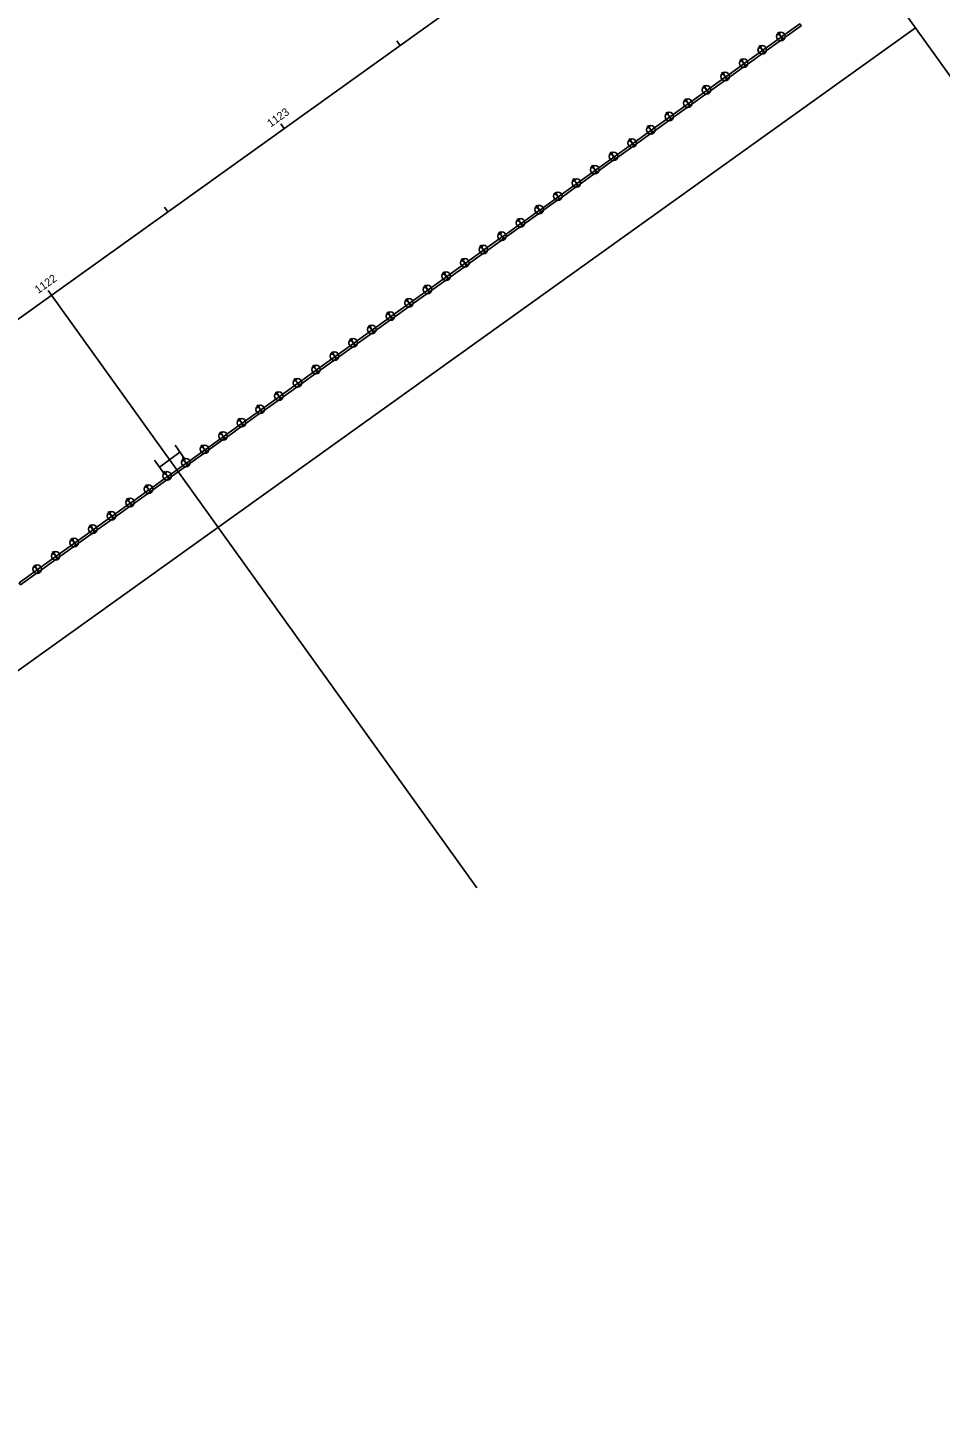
# Model space of a CAD drawing. Extents: x 2079879 to 2092887, y 778083 to 784051.
# Drawn here: x 2084142 to 2084461, y 780721.7 to 781206.9 of the extents above; entities that cross this region are included whole.
import ezdxf

# ---------------------------------------------------------------- set-up
doc = ezdxf.new("R2010")
doc.units = 0
for name, color, linetype in [('SC_Scratch1', 7, 'Continuous'), ('SH_Data', 7, 'Continuous'), ('SH_Text', 7, 'Continuous'), ('XS_X_Pavt', 7, 'Continuous')]:
    doc.layers.add(name, color=color, linetype=linetype)

msp = doc.modelspace()

# ---------------------------------------------------------------- linework, layer by layer
at = {"layer": 'SC_Scratch1'}
for p, q in [((2079923.52, 778084.44), (2085691.45, 782217.74)), ((2084272.23, 781200.72), (2084271.06, 781202.35)), ((2084231.59, 781171.6), (2084230.42, 781173.22)), ((2084190.94, 781142.47), (2084189.78, 781144.1)), ((2084150.3, 781113.35), (2084149.14, 781114.97))]:
    msp.add_line(p, q, dxfattribs=at)
at = {"layer": 'SH_Data'}
for p, q in [((2084394.15, 781288.09), (2084523.01, 781108.28)), ((2083962.54, 780855.77), (2084452.4, 781206.81)), ((2084404.67, 781204.74), (2084404.24, 781205.35)), ((2084398.17, 781200.08), (2084397.74, 781200.69)), ((2084391.67, 781195.42), (2084391.24, 781196.03)), ((2084385.17, 781190.76), (2084384.73, 781191.37)), ((2084378.66, 781186.1), (2084378.23, 781186.71)), ((2084365.66, 781176.78), (2084365.22, 781177.39)), ((2084372.16, 781181.44), (2084371.73, 781182.05)), ((2084359.15, 781172.12), (2084358.72, 781172.74)), ((2084352.65, 781167.46), (2084352.22, 781168.08)), ((2084346.15, 781162.8), (2084345.72, 781163.42)), ((2084339.65, 781158.14), (2084339.21, 781158.76)), ((2084333.14, 781153.48), (2084332.71, 781154.1)), ((2084320.14, 781144.16), (2084319.71, 781144.78)), ((2084313.64, 781139.5), (2084313.2, 781140.12)), ((2084307.13, 781134.84), (2084306.7, 781135.46)), ((2084300.63, 781130.18), (2084300.2, 781130.8)), ((2084294.13, 781125.52), (2084293.69, 781126.14)), ((2084287.62, 781120.86), (2084287.19, 781121.48)), ((2084281.12, 781116.2), (2084280.69, 781116.82)), ((2084150.3, 781113.35), (2084298.97, 780905.89)), ((2084268.12, 781106.88), (2084267.68, 781107.5)), ((2084261.61, 781102.22), (2084261.18, 781102.84)), ((2084255.11, 781097.56), (2084254.68, 781098.18)), ((2084248.61, 781092.9), (2084248.18, 781093.52)), ((2084242.1, 781088.24), (2084241.67, 781088.86)), ((2084235.6, 781083.58), (2084235.17, 781084.2)), ((2084229.1, 781078.92), (2084228.67, 781079.54)), ((2084222.6, 781074.27), (2084222.16, 781074.88)), ((2084216.09, 781069.61), (2084215.66, 781070.22)), ((2084203.09, 781060.29), (2084202.66, 781060.9)), ((2084195.19, 781058.32), (2084188.01, 781053.17)), ((2084196.92, 781055.87), (2084193.47, 781060.77)), ((2084196.3, 781056.03), (2084196.01, 781056.44)), ((2084196.59, 781055.63), (2084196.3, 781056.03)), ((2084189.74, 781050.72), (2084186.29, 781055.63)), ((2084189.79, 781051.37), (2084189.51, 781051.78)), ((2084190.08, 781050.97), (2084189.79, 781051.37)), ((2084183.58, 781046.31), (2084183.15, 781046.92)), ((2084177.08, 781041.65), (2084176.65, 781042.26)), ((2084170.57, 781036.99), (2084170.14, 781037.6)), ((2084164.07, 781032.33), (2084163.64, 781032.94)), ((2084157.57, 781027.67), (2084157.14, 781028.28)), ((2084151.07, 781023.01), (2084150.63, 781023.62))]:
    msp.add_line(p, q, dxfattribs=at)
at = {"layer": 'SH_Text'}
for centre in [(2084405.33, 781203.83), (2084398.82, 781199.17), (2084392.32, 781194.51), (2084385.82, 781189.85), (2084379.32, 781185.19), (2084366.31, 781175.87), (2084372.81, 781180.53), (2084359.81, 781171.21), (2084353.3, 781166.55), (2084346.8, 781161.89), (2084340.3, 781157.23), (2084333.8, 781152.57), (2084327.29, 781147.91), (2084320.79, 781143.25), (2084314.29, 781138.59), (2084307.79, 781133.93), (2084301.28, 781129.27), (2084294.78, 781124.61), (2084288.28, 781119.95), (2084281.77, 781115.29), (2084275.27, 781110.63), (2084268.77, 781105.97), (2084262.27, 781101.31), (2084255.76, 781096.65), (2084249.26, 781091.99), (2084242.76, 781087.33), (2084236.26, 781082.67), (2084229.75, 781078.01), (2084223.25, 781073.35), (2084216.75, 781068.69), (2084203.74, 781059.37), (2084210.24, 781064.03), (2084197.24, 781054.71), (2084190.74, 781050.05), (2084184.23, 781045.39), (2084177.73, 781040.73), (2084171.23, 781036.08), (2084164.72, 781031.42), (2084158.22, 781026.76), (2084151.72, 781022.1), (2084145.22, 781017.44)]:
    msp.add_circle(centre, 1.5, dxfattribs=at)
at = {"layer": 'XS_X_Pavt'}
for points in [[(2084405.54, 781203.68), (2084411.91, 781208.24), (2084412.39, 781207.56), (2084406.02, 781203)], [(2084399.04, 781199.02), (2084405.4, 781203.58), (2084405.89, 781202.9), (2084399.52, 781198.34)], [(2084404.33, 781204.5), (2084405.01, 781204.98), (2084405.04, 781204.95), (2084404.72, 781204.73), (2084405.98, 781202.97), (2084406.29, 781203.2), (2084406.32, 781203.16), (2084405.64, 781202.68), (2084405.62, 781202.71), (2084405.93, 781202.93), (2084404.67, 781204.69), (2084404.36, 781204.47)], [(2084392.53, 781194.36), (2084398.9, 781198.92), (2084399.38, 781198.24), (2084393.02, 781193.68)], [(2084397.83, 781199.84), (2084398.51, 781200.32), (2084398.53, 781200.29), (2084398.22, 781200.07), (2084399.48, 781198.31), (2084399.79, 781198.54), (2084399.82, 781198.5), (2084399.14, 781198.02), (2084399.11, 781198.05), (2084399.43, 781198.27), (2084398.17, 781200.03), (2084397.86, 781199.81)], [(2084386.03, 781189.7), (2084392.4, 781194.26), (2084392.88, 781193.58), (2084386.51, 781189.02)], [(2084391.33, 781195.18), (2084392.01, 781195.66), (2084392.03, 781195.63), (2084391.72, 781195.41), (2084392.98, 781193.65), (2084393.29, 781193.88), (2084393.31, 781193.84), (2084392.64, 781193.36), (2084392.61, 781193.39), (2084392.92, 781193.61), (2084391.67, 781195.37), (2084391.35, 781195.15)], [(2084379.53, 781185.04), (2084385.89, 781189.6), (2084386.38, 781188.92), (2084380.01, 781184.36)], [(2084384.83, 781190.52), (2084385.5, 781191), (2084385.53, 781190.97), (2084385.21, 781190.75), (2084386.47, 781188.99), (2084386.79, 781189.22), (2084386.81, 781189.18), (2084386.13, 781188.7), (2084386.11, 781188.73), (2084386.42, 781188.95), (2084385.16, 781190.71), (2084384.85, 781190.49)], [(2084373.02, 781180.38), (2084379.39, 781184.94), (2084379.88, 781184.26), (2084373.51, 781179.7)], [(2084378.32, 781185.86), (2084379, 781186.34), (2084379.02, 781186.31), (2084378.71, 781186.09), (2084379.97, 781184.33), (2084380.28, 781184.56), (2084380.31, 781184.52), (2084379.63, 781184.04), (2084379.61, 781184.07), (2084379.92, 781184.29), (2084378.66, 781186.05), (2084378.35, 781185.83)], [(2084366.52, 781175.72), (2084372.89, 781180.28), (2084373.37, 781179.6), (2084367.01, 781175.04)], [(2084371.82, 781181.2), (2084372.5, 781181.68), (2084372.52, 781181.65), (2084372.21, 781181.43), (2084373.47, 781179.67), (2084373.78, 781179.9), (2084373.8, 781179.86), (2084373.13, 781179.38), (2084373.1, 781179.41), (2084373.42, 781179.63), (2084372.16, 781181.39), (2084371.84, 781181.17)], [(2084360.02, 781171.06), (2084366.39, 781175.62), (2084366.87, 781174.94), (2084360.5, 781170.38)], [(2084365.32, 781176.54), (2084366, 781177.02), (2084366.02, 781176.99), (2084365.71, 781176.77), (2084366.96, 781175.01), (2084367.28, 781175.24), (2084367.3, 781175.2), (2084366.62, 781174.72), (2084366.6, 781174.75), (2084366.91, 781174.98), (2084365.66, 781176.73), (2084365.34, 781176.51)], [(2084352.31, 781167.22), (2084352.99, 781167.71), (2084353.01, 781167.67), (2084352.7, 781167.45), (2084353.96, 781165.69), (2084354.27, 781165.92), (2084354.3, 781165.88), (2084353.62, 781165.4), (2084353.59, 781165.43), (2084353.91, 781165.66), (2084352.65, 781167.41), (2084352.34, 781167.19)], [(2084353.52, 781166.4), (2084359.88, 781170.96), (2084360.37, 781170.28), (2084354, 781165.72)], [(2084358.82, 781171.88), (2084359.49, 781172.36), (2084359.52, 781172.33), (2084359.2, 781172.11), (2084360.46, 781170.35), (2084360.77, 781170.58), (2084360.8, 781170.54), (2084360.12, 781170.06), (2084360.1, 781170.09), (2084360.41, 781170.32), (2084359.15, 781172.07), (2084358.84, 781171.85)], [(2084345.81, 781162.56), (2084346.49, 781163.05), (2084346.51, 781163.01), (2084346.2, 781162.79), (2084347.46, 781161.03), (2084347.77, 781161.26), (2084347.79, 781161.22), (2084347.12, 781160.74), (2084347.09, 781160.77), (2084347.41, 781161), (2084346.15, 781162.75), (2084345.83, 781162.53)], [(2084347.01, 781161.74), (2084353.38, 781166.3), (2084353.87, 781165.62), (2084347.5, 781161.06)], [(2084339.31, 781157.9), (2084339.98, 781158.39), (2084340.01, 781158.35), (2084339.7, 781158.13), (2084340.95, 781156.37), (2084341.27, 781156.6), (2084341.29, 781156.56), (2084340.61, 781156.08), (2084340.59, 781156.11), (2084340.9, 781156.34), (2084339.64, 781158.09), (2084339.33, 781157.87)], [(2084340.51, 781157.08), (2084346.88, 781161.64), (2084347.36, 781160.97), (2084341, 781156.4)], [(2084332.8, 781153.24), (2084333.48, 781153.73), (2084333.51, 781153.69), (2084333.19, 781153.47), (2084334.45, 781151.71), (2084334.76, 781151.94), (2084334.79, 781151.9), (2084334.11, 781151.42), (2084334.09, 781151.45), (2084334.4, 781151.68), (2084333.14, 781153.43), (2084332.83, 781153.21)], [(2084334.01, 781152.42), (2084340.37, 781156.98), (2084340.86, 781156.31), (2084334.49, 781151.74)], [(2084326.3, 781148.58), (2084326.98, 781149.07), (2084327, 781149.03), (2084326.69, 781148.81), (2084327.95, 781147.05), (2084328.26, 781147.28), (2084328.28, 781147.24), (2084327.61, 781146.76), (2084327.58, 781146.79), (2084327.9, 781147.02), (2084326.64, 781148.77), (2084326.33, 781148.55)], [(2084327.5, 781147.76), (2084333.87, 781152.32), (2084334.36, 781151.65), (2084327.99, 781147.08)], [(2084319.8, 781143.92), (2084320.48, 781144.41), (2084320.5, 781144.37), (2084320.19, 781144.15), (2084321.44, 781142.39), (2084321.76, 781142.62), (2084321.78, 781142.58), (2084321.1, 781142.1), (2084321.08, 781142.13), (2084321.39, 781142.36), (2084320.14, 781144.11), (2084319.82, 781143.89)], [(2084321, 781143.1), (2084327.37, 781147.66), (2084327.85, 781146.99), (2084321.49, 781142.42)], [(2084313.3, 781139.26), (2084313.97, 781139.75), (2084314, 781139.71), (2084313.68, 781139.49), (2084314.94, 781137.73), (2084315.26, 781137.96), (2084315.28, 781137.92), (2084314.6, 781137.44), (2084314.58, 781137.47), (2084314.89, 781137.7), (2084313.63, 781139.45), (2084313.32, 781139.23)], [(2084314.5, 781138.44), (2084320.87, 781143), (2084321.35, 781142.33), (2084314.98, 781137.76)], [(2084301.49, 781129.12), (2084307.86, 781133.68), (2084308.35, 781133.01), (2084301.98, 781128.44)], [(2084306.79, 781134.6), (2084307.47, 781135.09), (2084307.49, 781135.05), (2084307.18, 781134.83), (2084308.44, 781133.07), (2084308.75, 781133.3), (2084308.78, 781133.26), (2084308.1, 781132.78), (2084308.08, 781132.81), (2084308.39, 781133.04), (2084307.13, 781134.79), (2084306.82, 781134.57)], [(2084308, 781133.78), (2084314.36, 781138.34), (2084314.85, 781137.67), (2084308.48, 781133.1)], [(2084294.99, 781124.46), (2084301.36, 781129.02), (2084301.84, 781128.35), (2084295.48, 781123.78)], [(2084300.29, 781129.94), (2084300.97, 781130.43), (2084300.99, 781130.39), (2084300.68, 781130.17), (2084301.94, 781128.41), (2084302.25, 781128.64), (2084302.27, 781128.6), (2084301.6, 781128.12), (2084301.57, 781128.15), (2084301.89, 781128.38), (2084300.63, 781130.13), (2084300.31, 781129.91)], [(2084288.49, 781119.8), (2084294.86, 781124.36), (2084295.34, 781123.69), (2084288.97, 781119.12)], [(2084293.79, 781125.28), (2084294.47, 781125.77), (2084294.49, 781125.73), (2084294.18, 781125.51), (2084295.43, 781123.75), (2084295.75, 781123.98), (2084295.77, 781123.94), (2084295.09, 781123.46), (2084295.07, 781123.49), (2084295.38, 781123.72), (2084294.13, 781125.47), (2084293.81, 781125.25)], [(2084281.99, 781115.14), (2084288.35, 781119.7), (2084288.84, 781119.03), (2084282.47, 781114.46)], [(2084287.29, 781120.62), (2084287.96, 781121.11), (2084287.99, 781121.07), (2084287.67, 781120.85), (2084288.93, 781119.09), (2084289.24, 781119.32), (2084289.27, 781119.28), (2084288.59, 781118.8), (2084288.57, 781118.83), (2084288.88, 781119.06), (2084287.62, 781120.81), (2084287.31, 781120.59)], [(2084275.48, 781110.48), (2084281.85, 781115.04), (2084282.34, 781114.37), (2084275.97, 781109.8)], [(2084280.78, 781115.96), (2084281.46, 781116.45), (2084281.48, 781116.41), (2084281.17, 781116.19), (2084282.43, 781114.43), (2084282.74, 781114.66), (2084282.77, 781114.62), (2084282.09, 781114.14), (2084282.06, 781114.17), (2084282.38, 781114.4), (2084281.12, 781116.15), (2084280.81, 781115.93)], [(2084268.98, 781105.82), (2084275.35, 781110.38), (2084275.83, 781109.71), (2084269.47, 781105.14)], [(2084274.28, 781111.3), (2084274.96, 781111.79), (2084274.98, 781111.75), (2084274.67, 781111.53), (2084275.93, 781109.77), (2084276.24, 781110), (2084276.26, 781109.96), (2084275.59, 781109.48), (2084275.56, 781109.51), (2084275.88, 781109.74), (2084274.62, 781111.49), (2084274.3, 781111.27)], [(2084262.48, 781101.16), (2084268.84, 781105.72), (2084269.33, 781105.05), (2084262.96, 781100.48)], [(2084267.78, 781106.64), (2084268.45, 781107.13), (2084268.48, 781107.09), (2084268.16, 781106.87), (2084269.42, 781105.11), (2084269.74, 781105.34), (2084269.76, 781105.3), (2084269.08, 781104.82), (2084269.06, 781104.85), (2084269.37, 781105.08), (2084268.11, 781106.83), (2084267.8, 781106.61)], [(2084255.97, 781096.5), (2084262.34, 781101.06), (2084262.83, 781100.39), (2084256.46, 781095.82)], [(2084261.27, 781101.98), (2084261.95, 781102.47), (2084261.98, 781102.43), (2084261.66, 781102.21), (2084262.92, 781100.45), (2084263.23, 781100.68), (2084263.26, 781100.64), (2084262.58, 781100.16), (2084262.56, 781100.19), (2084262.87, 781100.42), (2084261.61, 781102.17), (2084261.3, 781101.95)], [(2084249.47, 781091.84), (2084255.84, 781096.4), (2084256.32, 781095.73), (2084249.96, 781091.16)], [(2084254.77, 781097.32), (2084255.45, 781097.81), (2084255.47, 781097.77), (2084255.16, 781097.55), (2084256.42, 781095.79), (2084256.73, 781096.02), (2084256.75, 781095.98), (2084256.08, 781095.5), (2084256.05, 781095.53), (2084256.37, 781095.76), (2084255.11, 781097.51), (2084254.8, 781097.29)], [(2084242.97, 781087.18), (2084249.34, 781091.74), (2084249.82, 781091.07), (2084243.45, 781086.5)], [(2084248.27, 781092.66), (2084248.95, 781093.15), (2084248.97, 781093.11), (2084248.66, 781092.89), (2084249.91, 781091.13), (2084250.23, 781091.36), (2084250.25, 781091.33), (2084249.57, 781090.84), (2084249.55, 781090.87), (2084249.86, 781091.1), (2084248.61, 781092.85), (2084248.29, 781092.63)], [(2084236.47, 781082.52), (2084242.83, 781087.08), (2084243.32, 781086.41), (2084236.95, 781081.84)], [(2084241.77, 781088), (2084242.44, 781088.49), (2084242.47, 781088.45), (2084242.15, 781088.23), (2084243.41, 781086.47), (2084243.73, 781086.7), (2084243.75, 781086.67), (2084243.07, 781086.18), (2084243.05, 781086.21), (2084243.36, 781086.44), (2084242.1, 781088.19), (2084241.79, 781087.97)], [(2084229.96, 781077.86), (2084236.33, 781082.42), (2084236.82, 781081.75), (2084230.45, 781077.18)], [(2084235.26, 781083.34), (2084235.94, 781083.83), (2084235.96, 781083.79), (2084235.65, 781083.57), (2084236.91, 781081.81), (2084237.22, 781082.04), (2084237.25, 781082.01), (2084236.57, 781081.52), (2084236.55, 781081.55), (2084236.86, 781081.78), (2084235.6, 781083.53), (2084235.29, 781083.31)], [(2084223.46, 781073.2), (2084229.83, 781077.76), (2084230.31, 781077.09), (2084223.95, 781072.52)], [(2084228.76, 781078.68), (2084229.44, 781079.17), (2084229.46, 781079.13), (2084229.15, 781078.91), (2084230.41, 781077.15), (2084230.72, 781077.38), (2084230.74, 781077.35), (2084230.07, 781076.86), (2084230.04, 781076.89), (2084230.36, 781077.12), (2084229.1, 781078.87), (2084228.78, 781078.65)], [(2084216.96, 781068.54), (2084223.33, 781073.1), (2084223.81, 781072.43), (2084217.44, 781067.86)], [(2084222.26, 781074.02), (2084222.94, 781074.51), (2084222.96, 781074.47), (2084222.65, 781074.25), (2084223.9, 781072.49), (2084224.22, 781072.72), (2084224.24, 781072.69), (2084223.56, 781072.2), (2084223.54, 781072.23), (2084223.85, 781072.46), (2084222.6, 781074.21), (2084222.28, 781073.99)], [(2084210.46, 781063.88), (2084216.82, 781068.45), (2084217.31, 781067.77), (2084210.94, 781063.2)], [(2084215.76, 781069.36), (2084216.43, 781069.85), (2084216.46, 781069.81), (2084216.14, 781069.59), (2084217.4, 781067.83), (2084217.71, 781068.06), (2084217.74, 781068.03), (2084217.06, 781067.54), (2084217.04, 781067.57), (2084217.35, 781067.8), (2084216.09, 781069.55), (2084215.78, 781069.33)], [(2084203.95, 781059.22), (2084210.32, 781063.79), (2084210.81, 781063.11), (2084204.44, 781058.55)], [(2084209.25, 781064.7), (2084209.93, 781065.19), (2084209.95, 781065.15), (2084209.64, 781064.93), (2084210.9, 781063.17), (2084211.21, 781063.4), (2084211.24, 781063.37), (2084210.56, 781062.88), (2084210.53, 781062.91), (2084210.85, 781063.14), (2084209.59, 781064.89), (2084209.28, 781064.67)], [(2084197.45, 781054.56), (2084203.82, 781059.13), (2084204.3, 781058.45), (2084197.94, 781053.89)], [(2084202.75, 781060.04), (2084203.43, 781060.53), (2084203.45, 781060.49), (2084203.14, 781060.27), (2084204.4, 781058.51), (2084204.71, 781058.74), (2084204.73, 781058.71), (2084204.06, 781058.22), (2084204.03, 781058.25), (2084204.35, 781058.48), (2084203.09, 781060.23), (2084202.77, 781060.01)], [(2084189.74, 781050.72), (2084190.42, 781051.21), (2084190.45, 781051.18), (2084190.13, 781050.95), (2084191.39, 781049.19), (2084191.7, 781049.42), (2084191.73, 781049.39), (2084191.05, 781048.9), (2084191.03, 781048.93), (2084191.34, 781049.16), (2084190.08, 781050.91), (2084189.77, 781050.69)], [(2084190.95, 781049.9), (2084197.31, 781054.47), (2084197.8, 781053.79), (2084191.43, 781049.23)], [(2084196.25, 781055.38), (2084196.92, 781055.87), (2084196.95, 781055.84), (2084196.63, 781055.61), (2084197.89, 781053.85), (2084198.21, 781054.08), (2084198.23, 781054.05), (2084197.55, 781053.56), (2084197.53, 781053.59), (2084197.84, 781053.82), (2084196.58, 781055.57), (2084196.27, 781055.35)], [(2084183.24, 781046.06), (2084183.92, 781046.55), (2084183.94, 781046.52), (2084183.63, 781046.29), (2084184.89, 781044.54), (2084185.2, 781044.76), (2084185.22, 781044.73), (2084184.55, 781044.24), (2084184.52, 781044.27), (2084184.84, 781044.5), (2084183.58, 781046.25), (2084183.27, 781046.03)], [(2084184.44, 781045.24), (2084190.81, 781049.81), (2084191.3, 781049.13), (2084184.93, 781044.57)], [(2084176.74, 781041.4), (2084177.42, 781041.89), (2084177.44, 781041.86), (2084177.13, 781041.63), (2084178.38, 781039.88), (2084178.7, 781040.1), (2084178.72, 781040.07), (2084178.04, 781039.58), (2084178.02, 781039.61), (2084178.33, 781039.84), (2084177.08, 781041.59), (2084176.76, 781041.37)], [(2084177.94, 781040.58), (2084184.31, 781045.15), (2084184.79, 781044.47), (2084178.43, 781039.91)], [(2084170.24, 781036.74), (2084170.91, 781037.23), (2084170.94, 781037.2), (2084170.62, 781036.97), (2084171.88, 781035.22), (2084172.2, 781035.44), (2084172.22, 781035.41), (2084171.54, 781034.92), (2084171.52, 781034.95), (2084171.83, 781035.18), (2084170.57, 781036.93), (2084170.26, 781036.71)], [(2084171.44, 781035.92), (2084177.81, 781040.49), (2084178.29, 781039.81), (2084171.92, 781035.25)], [(2084163.73, 781032.08), (2084164.41, 781032.57), (2084164.43, 781032.54), (2084164.12, 781032.31), (2084165.38, 781030.56), (2084165.69, 781030.78), (2084165.72, 781030.75), (2084165.04, 781030.26), (2084165.02, 781030.29), (2084165.33, 781030.52), (2084164.07, 781032.27), (2084163.76, 781032.05)], [(2084164.94, 781031.26), (2084171.3, 781035.83), (2084171.79, 781035.15), (2084165.42, 781030.59)], [(2084157.23, 781027.42), (2084157.91, 781027.91), (2084157.93, 781027.88), (2084157.62, 781027.65), (2084158.88, 781025.9), (2084159.19, 781026.12), (2084159.21, 781026.09), (2084158.54, 781025.6), (2084158.51, 781025.63), (2084158.83, 781025.86), (2084157.57, 781027.62), (2084157.25, 781027.39)], [(2084158.43, 781026.6), (2084164.8, 781031.17), (2084165.29, 781030.49), (2084158.92, 781025.93)], [(2084150.73, 781022.76), (2084151.41, 781023.25), (2084151.43, 781023.22), (2084151.12, 781022.99), (2084152.37, 781021.24), (2084152.69, 781021.46), (2084152.71, 781021.43), (2084152.03, 781020.94), (2084152.01, 781020.97), (2084152.32, 781021.2), (2084151.07, 781022.96), (2084150.75, 781022.73)], [(2084151.93, 781021.94), (2084158.3, 781026.51), (2084158.78, 781025.83), (2084152.42, 781021.27)], [(2084138.93, 781012.62), (2084145.29, 781017.19), (2084145.78, 781016.51), (2084139.41, 781011.95)], [(2084144.23, 781018.1), (2084144.9, 781018.59), (2084144.93, 781018.56), (2084144.61, 781018.33), (2084145.87, 781016.58), (2084146.18, 781016.8), (2084146.21, 781016.77), (2084145.53, 781016.28), (2084145.51, 781016.32), (2084145.82, 781016.54), (2084144.56, 781018.3), (2084144.25, 781018.07)], [(2084145.43, 781017.28), (2084151.8, 781021.85), (2084152.28, 781021.17), (2084145.91, 781016.61)]]:
    msp.add_lwpolyline(points, close=True, dxfattribs=at)

# ---------------------------------------------------------------- texts
at = {"layer": 'SC_Scratch1'}
for s, p in [('1123', (2084226.92, 781171.94)), ('1122', (2084145.66, 781113.71))]:
    msp.add_text(s, height=2.8, rotation=35.6254, dxfattribs=at).set_placement(p)

doc.saveas('drawing.dxf')
